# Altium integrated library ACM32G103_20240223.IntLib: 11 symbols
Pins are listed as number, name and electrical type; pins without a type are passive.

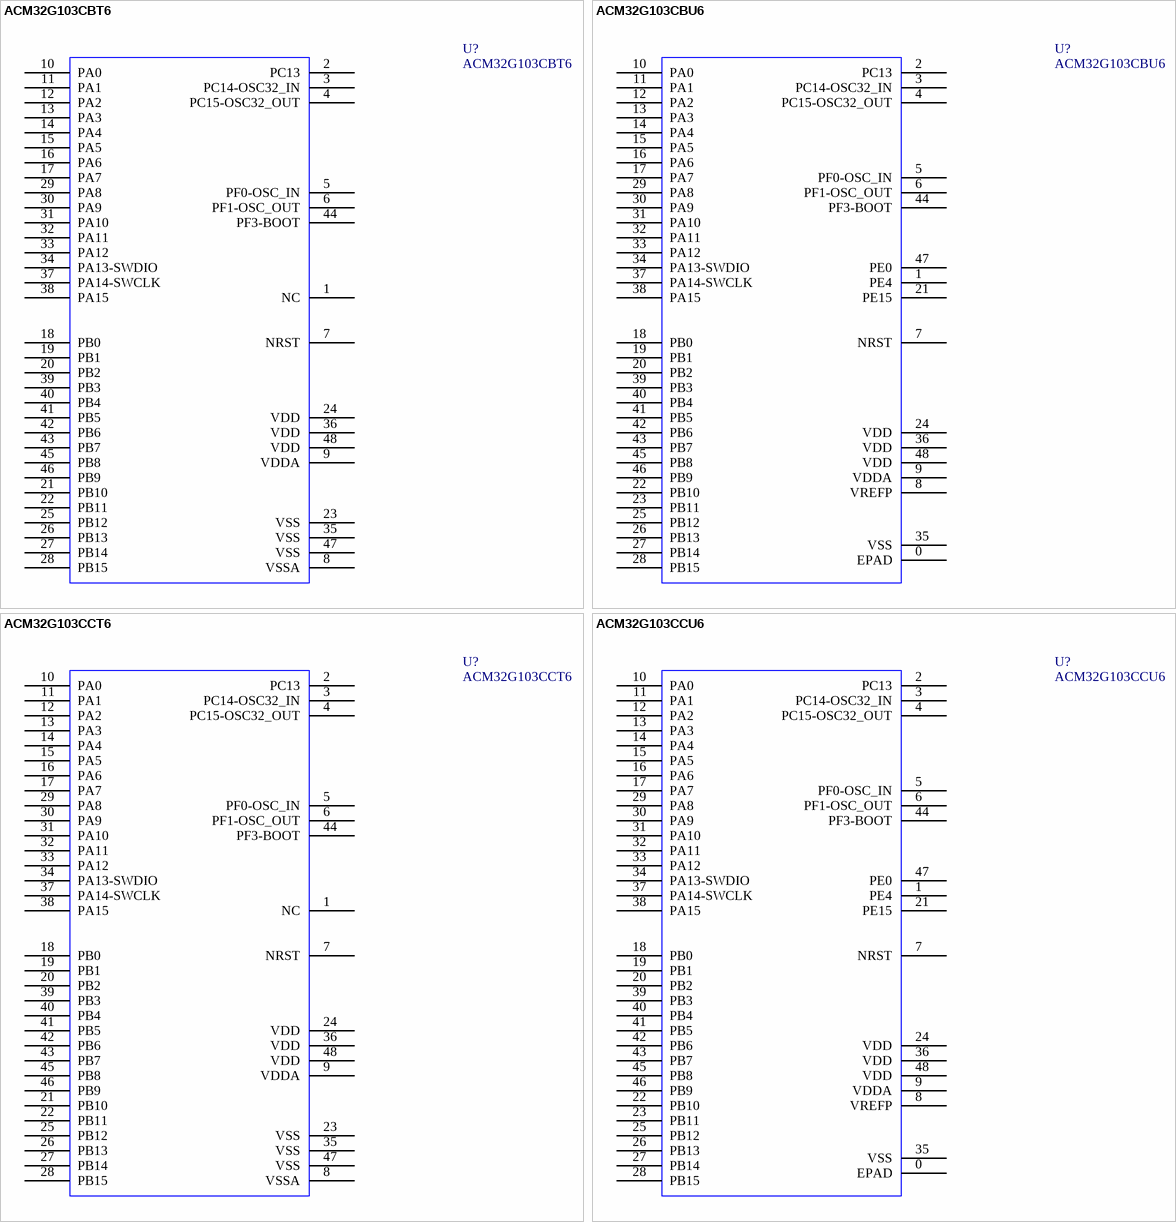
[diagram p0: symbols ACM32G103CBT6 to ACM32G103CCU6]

## ACM32G103CBT6
designator U?
Advanced ARM based 32-bit Cortex M33 MCU with 128 Kbytes Flash and 32 Kbytes of SRAM
footprint QFP-48_7x7/P.5 (QFP; 48 Leads; Body 7 x 7 mm; Pitch 0.5 mm)
pins: 1 NC, 2 PC13, 3 PC14-OSC32_IN, 4 PC15-OSC32_OUT, 5 PF0-OSC_IN, 6 PF1-OSC_OUT, 7 NRST, 8 VSSA, 9 VDDA, 10 PA0, 11 PA1, 12 PA2, 13 PA3, 14 PA4, 15 PA5, 16 PA6, 17 PA7, 18 PB0, 19 PB1, 20 PB2, 21 PB10, 22 PB11, 23 VSS, 24 VDD, 25 PB12, 26 PB13, 27 PB14, 28 PB15, 29 PA8, 30 PA9, 31 PA10, 32 PA11, 33 PA12, 34 PA13-SWDIO, 35 VSS, 36 VDD, 37 PA14-SWCLK, 38 PA15, 39 PB3, 40 PB4, 41 PB5, 42 PB6, 43 PB7, 44 PF3-BOOT, 45 PB8, 46 PB9, 47 VSS, 48 VDD

## ACM32G103CBU6
designator U?
Advanced ARM based 32-bit Cortex M33 MCU with 128 Kbytes Flash and 32 Kbytes of SRAM
footprint QFN-48_5x5/P.35 (QFN; 48 Leads; Body 5 x 5 mm; Pitch 0.35 mm)
pins: 0 EPAD, 1 PE4, 2 PC13, 3 PC14-OSC32_IN, 4 PC15-OSC32_OUT, 5 PF0-OSC_IN, 6 PF1-OSC_OUT, 7 NRST, 8 VREFP, 9 VDDA, 10 PA0, 11 PA1, 12 PA2, 13 PA3, 14 PA4, 15 PA5, 16 PA6, 17 PA7, 18 PB0, 19 PB1, 20 PB2, 21 PE15, 22 PB10, 23 PB11, 24 VDD, 25 PB12, 26 PB13, 27 PB14, 28 PB15, 29 PA8, 30 PA9, 31 PA10, 32 PA11, 33 PA12, 34 PA13-SWDIO, 35 VSS, 36 VDD, 37 PA14-SWCLK, 38 PA15, 39 PB3, 40 PB4, 41 PB5, 42 PB6, 43 PB7, 44 PF3-BOOT, 45 PB8, 46 PB9, 47 PE0, 48 VDD

## ACM32G103CCT6
designator U?
Advanced ARM based 32-bit Cortex M33 MCU with 320 Kbytes Flash and 64 Kbytes of SRAM
footprint QFP-48_7x7/P.5 (QFP; 48 Leads; Body 7 x 7 mm; Pitch 0.5 mm)
pins: 1 NC, 2 PC13, 3 PC14-OSC32_IN, 4 PC15-OSC32_OUT, 5 PF0-OSC_IN, 6 PF1-OSC_OUT, 7 NRST, 8 VSSA, 9 VDDA, 10 PA0, 11 PA1, 12 PA2, 13 PA3, 14 PA4, 15 PA5, 16 PA6, 17 PA7, 18 PB0, 19 PB1, 20 PB2, 21 PB10, 22 PB11, 23 VSS, 24 VDD, 25 PB12, 26 PB13, 27 PB14, 28 PB15, 29 PA8, 30 PA9, 31 PA10, 32 PA11, 33 PA12, 34 PA13-SWDIO, 35 VSS, 36 VDD, 37 PA14-SWCLK, 38 PA15, 39 PB3, 40 PB4, 41 PB5, 42 PB6, 43 PB7, 44 PF3-BOOT, 45 PB8, 46 PB9, 47 VSS, 48 VDD

## ACM32G103CCU6
designator U?
Advanced ARM based 32-bit Cortex M33 MCU with 320 Kbytes Flash and 64 Kbytes of SRAM
footprint QFN-48_5x5/P.35 (QFN; 48 Leads; Body 5 x 5 mm; Pitch 0.35 mm)
pins: 0 EPAD, 1 PE4, 2 PC13, 3 PC14-OSC32_IN, 4 PC15-OSC32_OUT, 5 PF0-OSC_IN, 6 PF1-OSC_OUT, 7 NRST, 8 VREFP, 9 VDDA, 10 PA0, 11 PA1, 12 PA2, 13 PA3, 14 PA4, 15 PA5, 16 PA6, 17 PA7, 18 PB0, 19 PB1, 20 PB2, 21 PE15, 22 PB10, 23 PB11, 24 VDD, 25 PB12, 26 PB13, 27 PB14, 28 PB15, 29 PA8, 30 PA9, 31 PA10, 32 PA11, 33 PA12, 34 PA13-SWDIO, 35 VSS, 36 VDD, 37 PA14-SWCLK, 38 PA15, 39 PB3, 40 PB4, 41 PB5, 42 PB6, 43 PB7, 44 PF3-BOOT, 45 PB8, 46 PB9, 47 PE0, 48 VDD

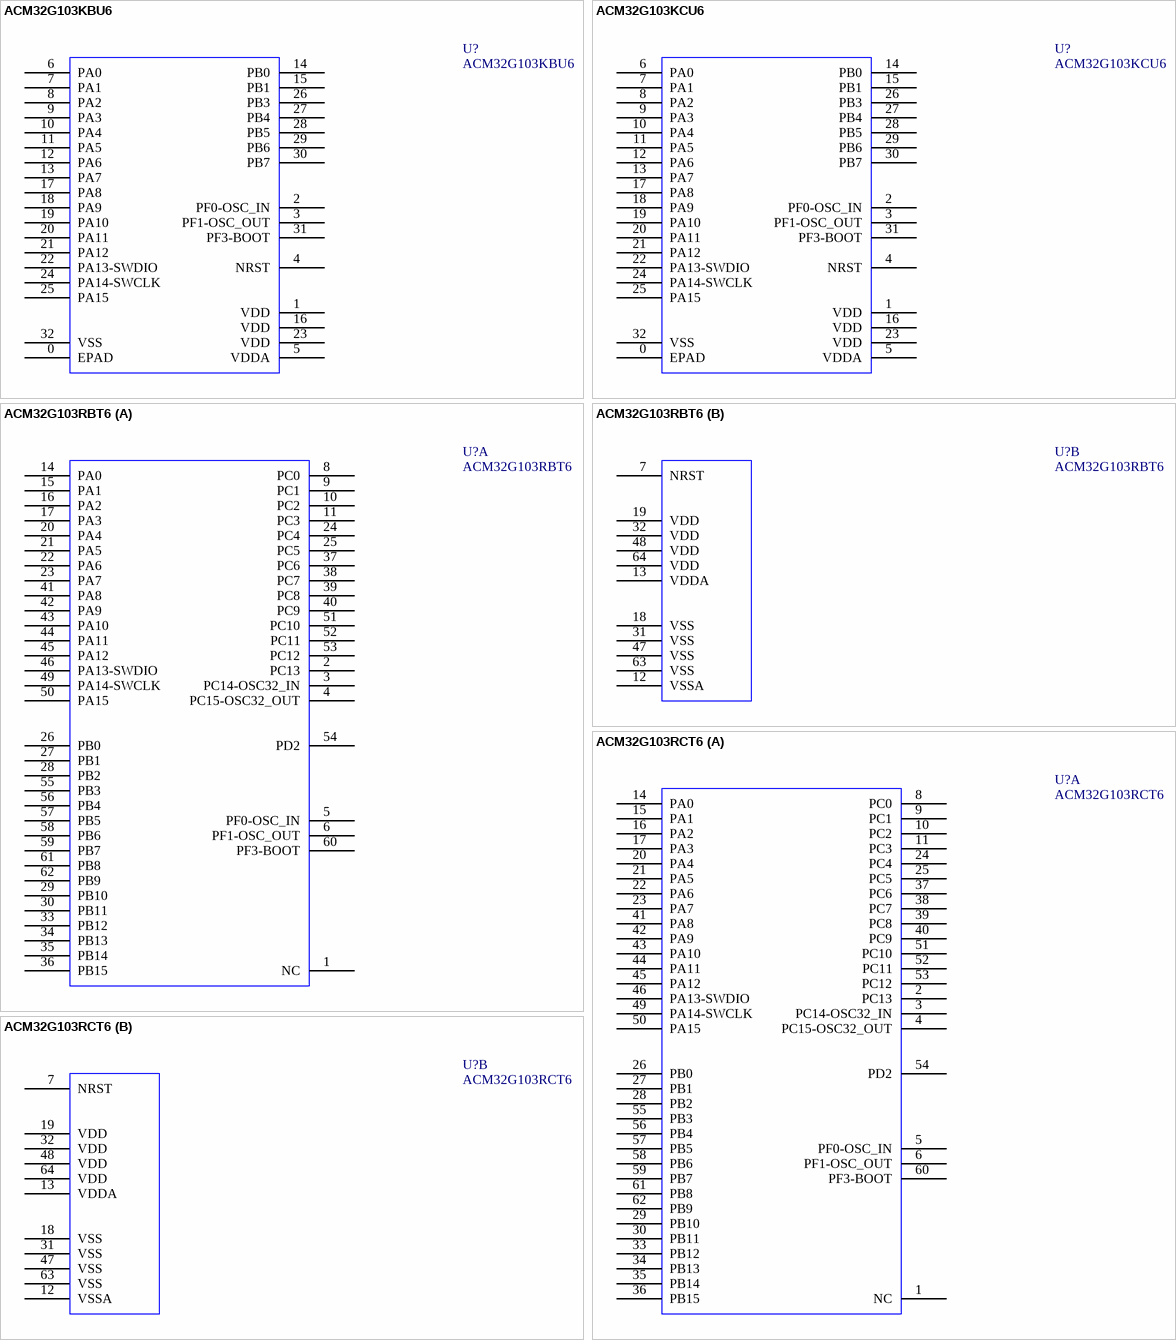
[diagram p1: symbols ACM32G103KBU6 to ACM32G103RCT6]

## ACM32G103KBU6
designator U?
Advanced ARM based 32-bit Cortex M33 MCU with 128 Kbytes Flash and 32 Kbytes of SRAM
footprint QFN-32_4X4/P.4 (QFN; 32 Leads; Body 4 x 4 mm; Pitch 0.4 mm)
pins: 0 EPAD, 1 VDD, 2 PF0-OSC_IN, 3 PF1-OSC_OUT, 4 NRST, 5 VDDA, 6 PA0, 7 PA1, 8 PA2, 9 PA3, 10 PA4, 11 PA5, 12 PA6, 13 PA7, 14 PB0, 15 PB1, 16 VDD, 17 PA8, 18 PA9, 19 PA10, 20 PA11, 21 PA12, 22 PA13-SWDIO, 23 VDD, 24 PA14-SWCLK, 25 PA15, 26 PB3, 27 PB4, 28 PB5, 29 PB6, 30 PB7, 31 PF3-BOOT, 32 VSS

## ACM32G103KCU6
designator U?
Advanced ARM based 32-bit Cortex M33 MCU with 320 Kbytes Flash and 64 Kbytes of SRAM
footprint QFN-32_4X4/P.4 (QFN; 32 Leads; Body 4 x 4 mm; Pitch 0.4 mm)
pins: 0 EPAD, 1 VDD, 2 PF0-OSC_IN, 3 PF1-OSC_OUT, 4 NRST, 5 VDDA, 6 PA0, 7 PA1, 8 PA2, 9 PA3, 10 PA4, 11 PA5, 12 PA6, 13 PA7, 14 PB0, 15 PB1, 16 VDD, 17 PA8, 18 PA9, 19 PA10, 20 PA11, 21 PA12, 22 PA13-SWDIO, 23 VDD, 24 PA14-SWCLK, 25 PA15, 26 PB3, 27 PB4, 28 PB5, 29 PB6, 30 PB7, 31 PF3-BOOT, 32 VSS

## ACM32G103RBT6
designator U?
Advanced ARM based 32-bit Cortex M33 MCU with 128 Kbytes Flash and 32 Kbytes of SRAM
footprint QFP-64_10x10/P.5 (QFP; 64 Leads; Body 10 x 10 mm; Pitch 0.5 mm)
part A pins: 1 NC, 2 PC13, 3 PC14-OSC32_IN, 4 PC15-OSC32_OUT, 5 PF0-OSC_IN, 6 PF1-OSC_OUT, 8 PC0, 9 PC1, 10 PC2, 11 PC3, 14 PA0, 15 PA1, 16 PA2, 17 PA3, 20 PA4, 21 PA5, 22 PA6, 23 PA7, 24 PC4, 25 PC5, 26 PB0, 27 PB1, 28 PB2, 29 PB10, 30 PB11, 33 PB12, 34 PB13, 35 PB14, 36 PB15, 37 PC6, 38 PC7, 39 PC8, 40 PC9, 41 PA8, 42 PA9, 43 PA10, 44 PA11, 45 PA12, 46 PA13-SWDIO, 49 PA14-SWCLK, 50 PA15, 51 PC10, 52 PC11, 53 PC12, 54 PD2, 55 PB3, 56 PB4, 57 PB5, 58 PB6, 59 PB7, 60 PF3-BOOT, 61 PB8, 62 PB9
part B pins: 7 NRST, 12 VSSA, 13 VDDA, 18 VSS, 19 VDD, 31 VSS, 32 VDD, 47 VSS, 48 VDD, 63 VSS, 64 VDD

## ACM32G103RCT6
designator U?
Advanced ARM based 32-bit Cortex M33 MCU with 320 Kbytes Flash and 64 Kbytes of SRAM
footprint QFP-64_10x10/P.5 (QFP; 64 Leads; Body 10 x 10 mm; Pitch 0.5 mm)
part A pins: 1 NC, 2 PC13, 3 PC14-OSC32_IN, 4 PC15-OSC32_OUT, 5 PF0-OSC_IN, 6 PF1-OSC_OUT, 8 PC0, 9 PC1, 10 PC2, 11 PC3, 14 PA0, 15 PA1, 16 PA2, 17 PA3, 20 PA4, 21 PA5, 22 PA6, 23 PA7, 24 PC4, 25 PC5, 26 PB0, 27 PB1, 28 PB2, 29 PB10, 30 PB11, 33 PB12, 34 PB13, 35 PB14, 36 PB15, 37 PC6, 38 PC7, 39 PC8, 40 PC9, 41 PA8, 42 PA9, 43 PA10, 44 PA11, 45 PA12, 46 PA13-SWDIO, 49 PA14-SWCLK, 50 PA15, 51 PC10, 52 PC11, 53 PC12, 54 PD2, 55 PB3, 56 PB4, 57 PB5, 58 PB6, 59 PB7, 60 PF3-BOOT, 61 PB8, 62 PB9
part B pins: 7 NRST, 12 VSSA, 13 VDDA, 18 VSS, 19 VDD, 31 VSS, 32 VDD, 47 VSS, 48 VDD, 63 VSS, 64 VDD

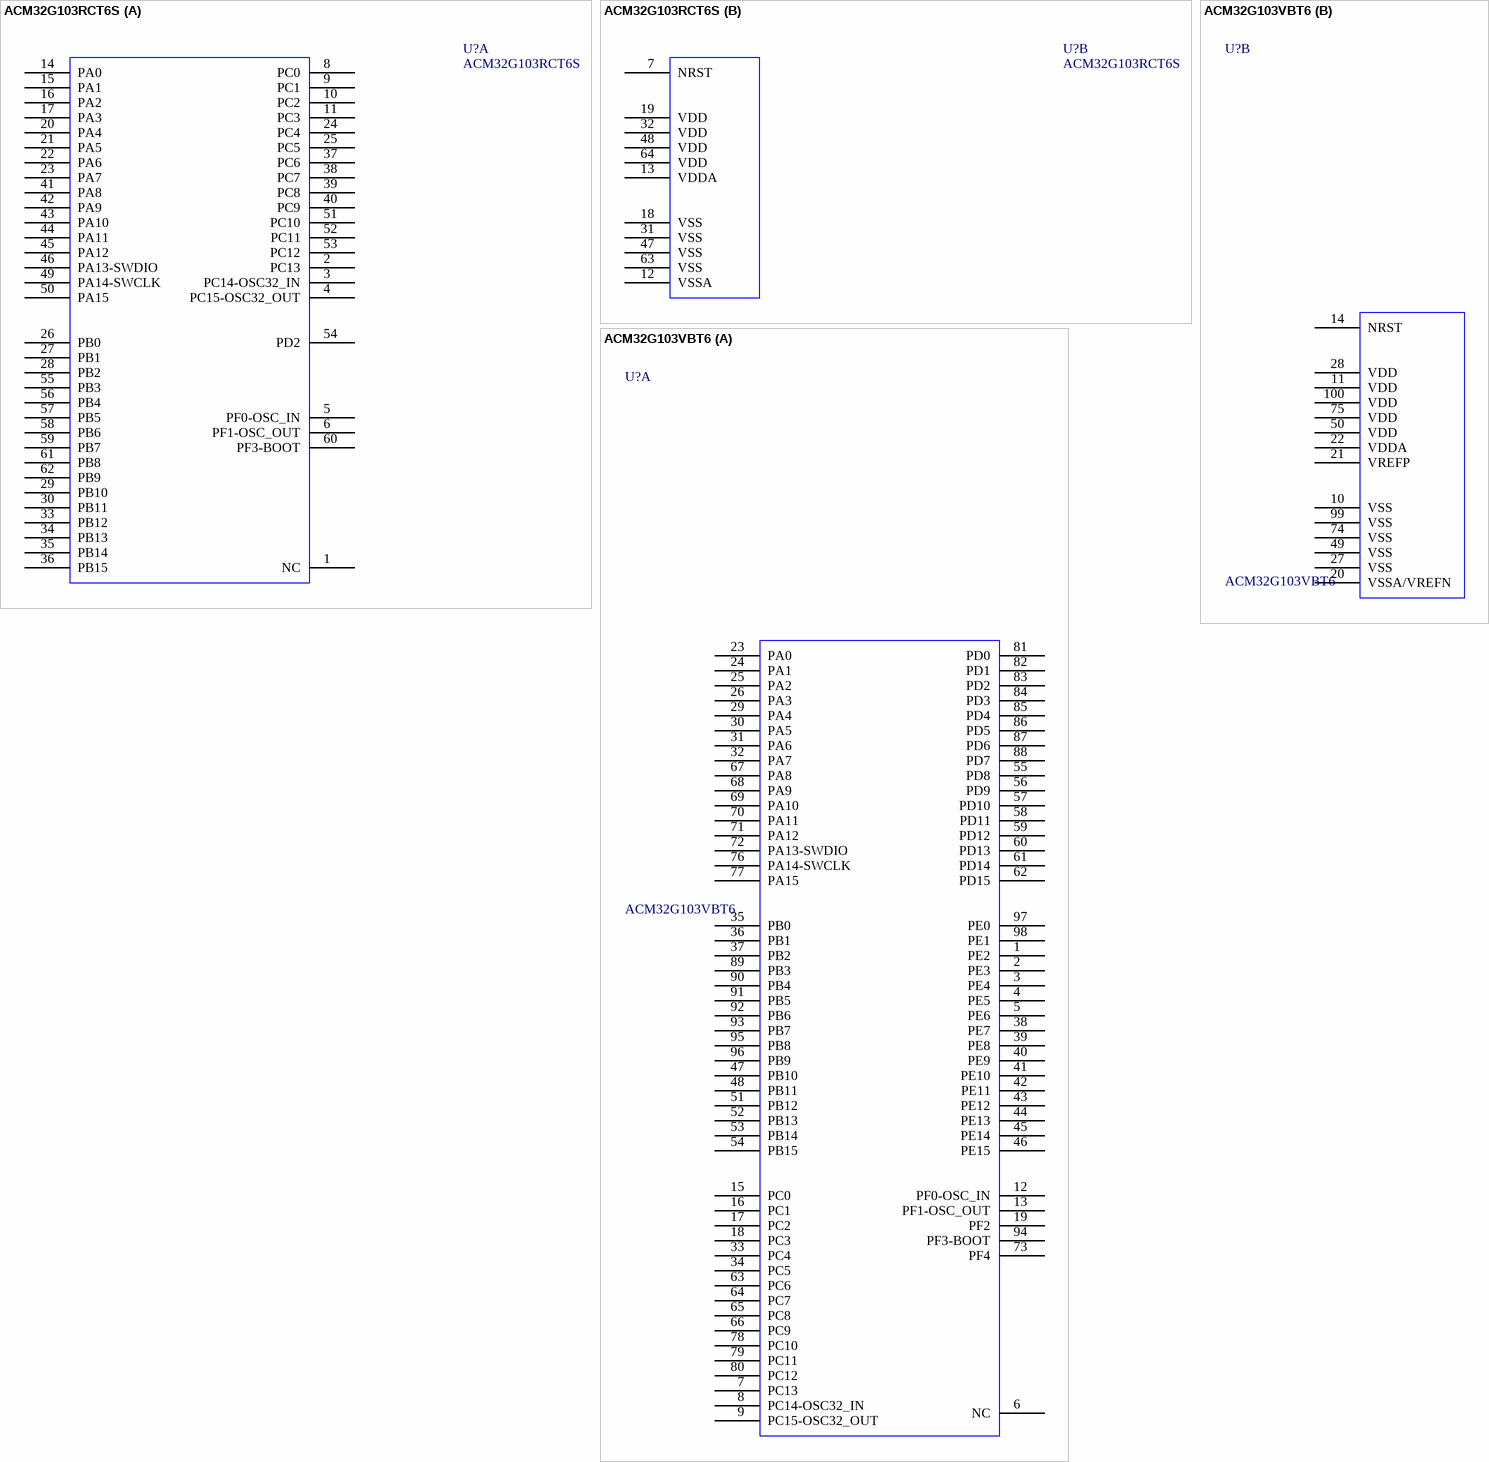
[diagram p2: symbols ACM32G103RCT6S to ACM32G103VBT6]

## ACM32G103RCT6S
designator U?
Advanced ARM based 32-bit Cortex M33 MCU with 320 Kbytes Flash and 64 Kbytes of SRAM
footprint QFP-64_7x7/P.4 (QFP; 64 Leads; Body 7 x 7 mm; Pitch 0.4 mm)
part A pins: 1 NC, 2 PC13, 3 PC14-OSC32_IN, 4 PC15-OSC32_OUT, 5 PF0-OSC_IN, 6 PF1-OSC_OUT, 8 PC0, 9 PC1, 10 PC2, 11 PC3, 14 PA0, 15 PA1, 16 PA2, 17 PA3, 20 PA4, 21 PA5, 22 PA6, 23 PA7, 24 PC4, 25 PC5, 26 PB0, 27 PB1, 28 PB2, 29 PB10, 30 PB11, 33 PB12, 34 PB13, 35 PB14, 36 PB15, 37 PC6, 38 PC7, 39 PC8, 40 PC9, 41 PA8, 42 PA9, 43 PA10, 44 PA11, 45 PA12, 46 PA13-SWDIO, 49 PA14-SWCLK, 50 PA15, 51 PC10, 52 PC11, 53 PC12, 54 PD2, 55 PB3, 56 PB4, 57 PB5, 58 PB6, 59 PB7, 60 PF3-BOOT, 61 PB8, 62 PB9
part B pins: 7 NRST, 12 VSSA, 13 VDDA, 18 VSS, 19 VDD, 31 VSS, 32 VDD, 47 VSS, 48 VDD, 63 VSS, 64 VDD

## ACM32G103VBT6
designator U?
Advanced ARM based 32-bit Cortex M33 MCU with 128 Kbytes Flash and 32 Kbytes of SRAM
footprint QFP-100_14X14/P.5 (QFP; 100 Leads; Body 14 x 14 mm; Pitch 0.5 mm)
part A pins: 1 PE2, 2 PE3, 3 PE4, 4 PE5, 5 PE6, 6 NC, 7 PC13, 8 PC14-OSC32_IN, 9 PC15-OSC32_OUT, 12 PF0-OSC_IN, 13 PF1-OSC_OUT, 15 PC0, 16 PC1, 17 PC2, 18 PC3, 19 PF2, 23 PA0, 24 PA1, 25 PA2, 26 PA3, 29 PA4, 30 PA5, 31 PA6, 32 PA7, 33 PC4, 34 PC5, 35 PB0, 36 PB1, 37 PB2, 38 PE7, 39 PE8, 40 PE9, 41 PE10, 42 PE11, 43 PE12, 44 PE13, 45 PE14, 46 PE15, 47 PB10, 48 PB11, 51 PB12, 52 PB13, 53 PB14, 54 PB15, 55 PD8, 56 PD9, 57 PD10, 58 PD11, 59 PD12, 60 PD13, 61 PD14, 62 PD15, 63 PC6, 64 PC7, 65 PC8, 66 PC9, 67 PA8, 68 PA9, 69 PA10, 70 PA11, 71 PA12, 72 PA13-SWDIO, 73 PF4, 76 PA14-SWCLK, 77 PA15, 78 PC10, 79 PC11, 80 PC12, 81 PD0, 82 PD1, 83 PD2, 84 PD3, 85 PD4, 86 PD5, 87 PD6, 88 PD7, 89 PB3, 90 PB4, 91 PB5, 92 PB6, 93 PB7, 94 PF3-BOOT, 95 PB8, 96 PB9, 97 PE0, 98 PE1
part B pins: 10 VSS, 11 VDD, 14 NRST, 20 VSSA/VREFN, 21 VREFP, 22 VDDA, 27 VSS, 28 VDD, 49 VSS, 50 VDD, 74 VSS, 75 VDD, 99 VSS, 100 VDD

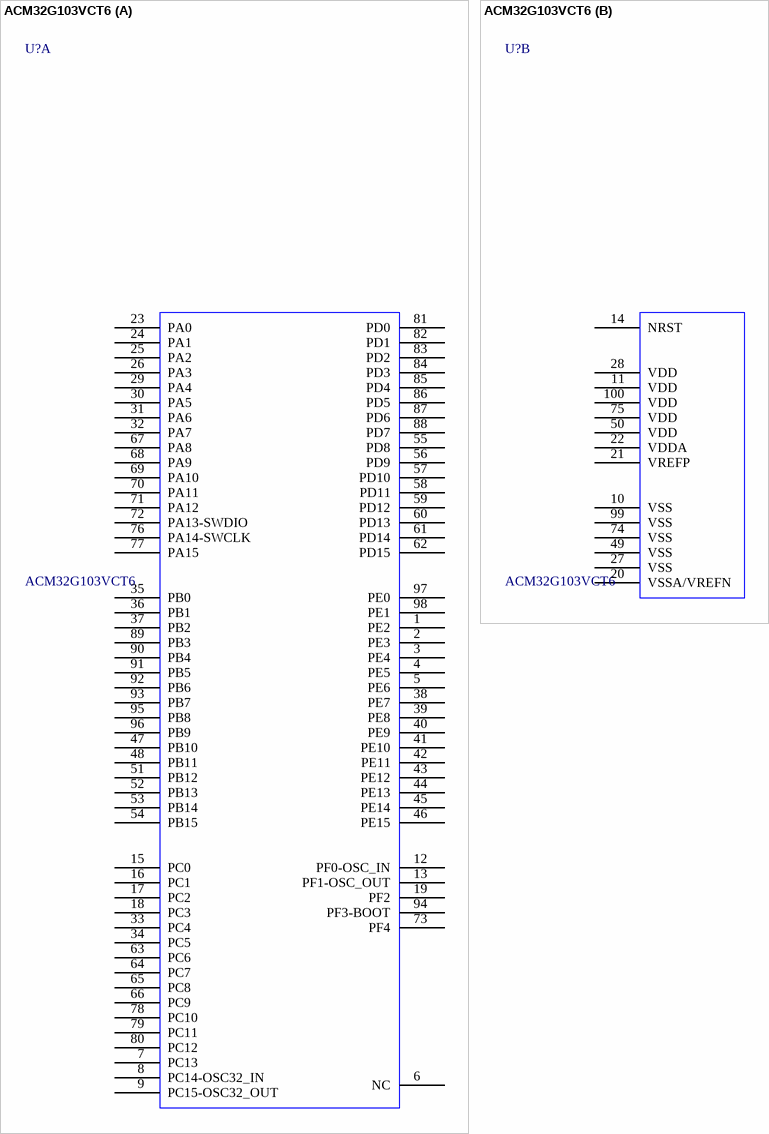
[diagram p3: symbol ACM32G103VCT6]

## ACM32G103VCT6
designator U?
Advanced ARM based 32-bit Cortex M33 MCU with 320 Kbytes Flash and 64 Kbytes of SRAM
footprint QFP-100_14X14/P.5 (QFP; 100 Leads; Body 14 x 14 mm; Pitch 0.5 mm)
part A pins: 1 PE2, 2 PE3, 3 PE4, 4 PE5, 5 PE6, 6 NC, 7 PC13, 8 PC14-OSC32_IN, 9 PC15-OSC32_OUT, 12 PF0-OSC_IN, 13 PF1-OSC_OUT, 15 PC0, 16 PC1, 17 PC2, 18 PC3, 19 PF2, 23 PA0, 24 PA1, 25 PA2, 26 PA3, 29 PA4, 30 PA5, 31 PA6, 32 PA7, 33 PC4, 34 PC5, 35 PB0, 36 PB1, 37 PB2, 38 PE7, 39 PE8, 40 PE9, 41 PE10, 42 PE11, 43 PE12, 44 PE13, 45 PE14, 46 PE15, 47 PB10, 48 PB11, 51 PB12, 52 PB13, 53 PB14, 54 PB15, 55 PD8, 56 PD9, 57 PD10, 58 PD11, 59 PD12, 60 PD13, 61 PD14, 62 PD15, 63 PC6, 64 PC7, 65 PC8, 66 PC9, 67 PA8, 68 PA9, 69 PA10, 70 PA11, 71 PA12, 72 PA13-SWDIO, 73 PF4, 76 PA14-SWCLK, 77 PA15, 78 PC10, 79 PC11, 80 PC12, 81 PD0, 82 PD1, 83 PD2, 84 PD3, 85 PD4, 86 PD5, 87 PD6, 88 PD7, 89 PB3, 90 PB4, 91 PB5, 92 PB6, 93 PB7, 94 PF3-BOOT, 95 PB8, 96 PB9, 97 PE0, 98 PE1
part B pins: 10 VSS, 11 VDD, 14 NRST, 20 VSSA/VREFN, 21 VREFP, 22 VDDA, 27 VSS, 28 VDD, 49 VSS, 50 VDD, 74 VSS, 75 VDD, 99 VSS, 100 VDD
